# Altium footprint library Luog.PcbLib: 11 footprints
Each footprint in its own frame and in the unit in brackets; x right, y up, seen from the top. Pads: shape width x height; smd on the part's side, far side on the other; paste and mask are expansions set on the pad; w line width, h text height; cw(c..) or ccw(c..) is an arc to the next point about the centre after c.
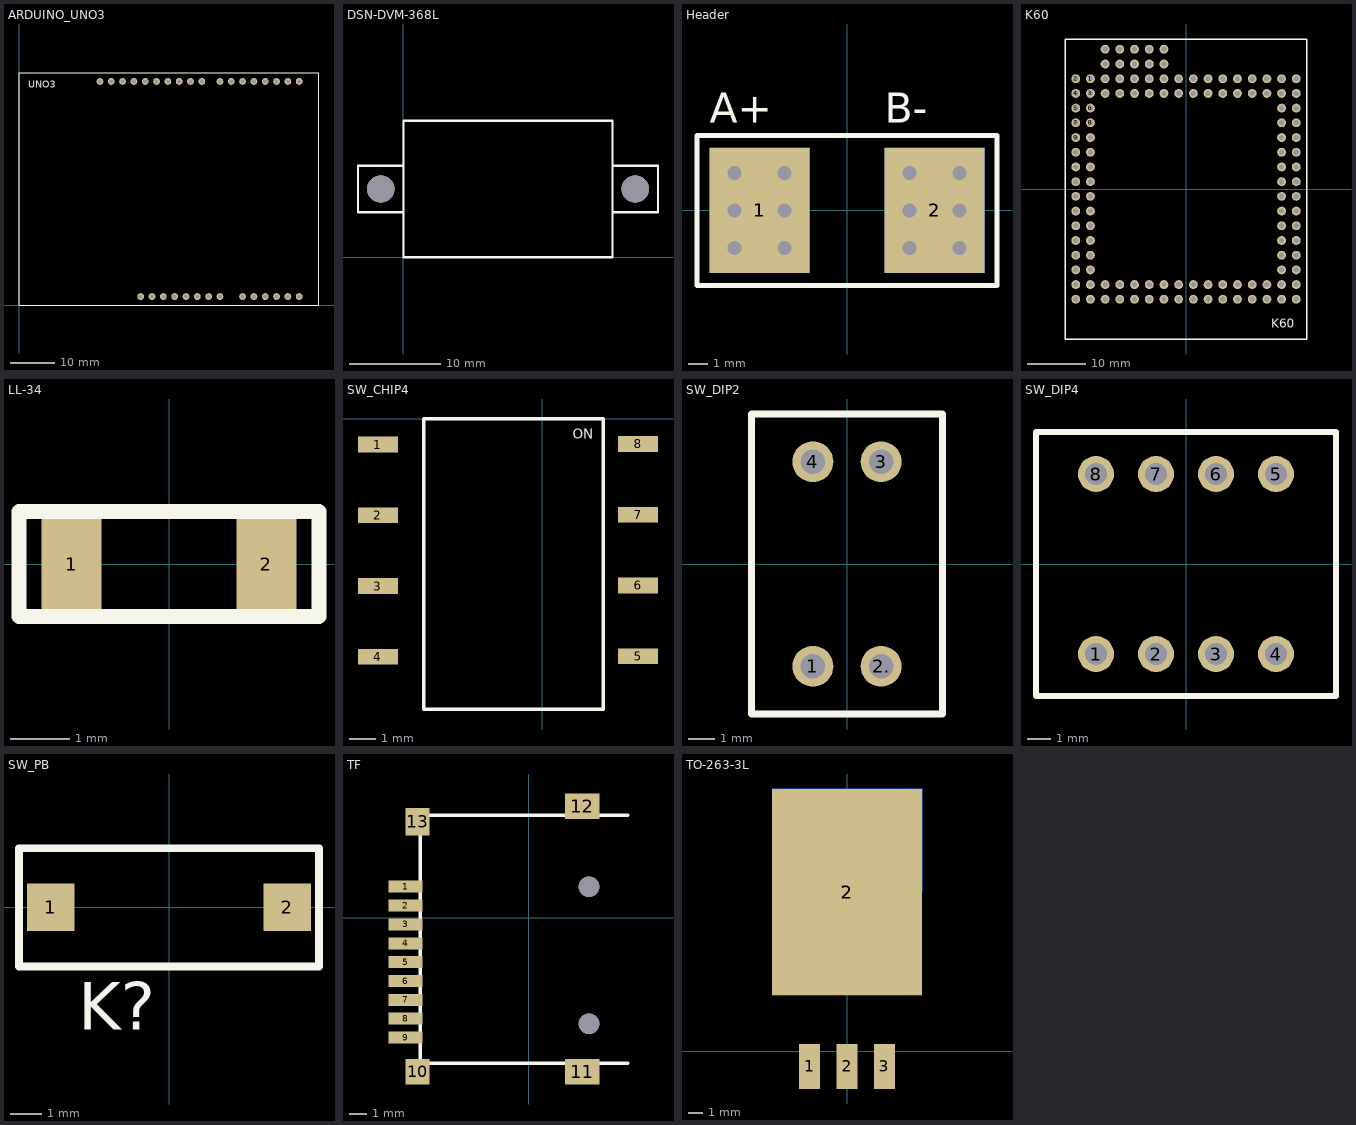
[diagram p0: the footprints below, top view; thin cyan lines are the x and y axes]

## ARDUINO_UNO3 [mil]
pads (32):
  round 60 hole 36: 1(2475,1975) 2(2375,1975) 3(2275,1975) 4(2175,1975) 5(2075,1975) 6(1975,1975) 7(1875,1975) 8(1775,1975) 9(1615,1975) 10(1515,1975) 11(1415,1975) 12(1315,1975) 13(1215,1975) 14(1115,1975) 15(1015,1975) 16(915,1975) 17(815,1975) 18(715,1975) 19(1075,75) 20(1175,75) 21(1275,75) 22(1375,75) 23(1475,75) 24(1575,75) 25(1675,75) 26(1775,75) 27(1975,75) 28(2075,75) 29(2175,75) 30(2275,75) 31(2375,75) 32(2475,75)
Top Overlay:
  lines w10: 0,0 0,2050 2650,2050 2650,0 0,0
  text "UNO3" at 80,1920 h60

## DSN-DVM-368L [mil]
height 393.7
via 1003.94,295.28 diameter 118.11 hole 118.11
via -98.43,295.28 diameter 118.11 hole 118.11
Top Overlay:
  lines w10: -0.67,395.67 -196.85,395.67 -196.85,194.88 -0.12,194.88 ; 905.63,194.88 1102.36,194.88 1102.36,395.67 906.18,395.67 ; 0,0 905.51,0 905.51,590.55 0,590.55 0,0

## Header [mil]
pads (4):
  rect 200x250 smd: 1(-175,0) 2(175,0)
  rect 200x250 smd far side: 1(-175,0) 2(175,0)
via -225,75 diameter 50 hole 28
via -125,75 diameter 50 hole 28
via -225,0 diameter 50 hole 28
via -125,0 diameter 50 hole 28
via -225,-75 diameter 50 hole 28
via -125,-75 diameter 50 hole 28
via 125,75 diameter 50 hole 28
via 225,75 diameter 50 hole 28
via 125,0 diameter 50 hole 28
via 125,-75 diameter 50 hole 28
via 225,0 diameter 50 hole 28
via 225,-75 diameter 50 hole 28
Top Overlay:
  lines w10: -300,-150 -300,150 185,150 300,150 300,-150 -185,-150 -300,-150
  text "B-" at 75,175 h60
  text "A+" at -275,175 h60

## K60 [mil]
pads (122):
  round 60 hole 36: 1(-650,750) 2(-750,750) 3(-650,650) 4(-750,650) 5(-750,550) 6(-650,550) 7(-750,450) 8(-650,450) 9(-750,350) 10(-650,350) 11(-750,250) 12(-650,250) 13(-750,150) 14(-650,150) 15(-750,50) 16(-650,50) 17(-650,-50) 18(-650,-150) 19(-750,-50) 20(-750,-150) 21(-750,-250) 22(-650,-250) 23(-750,-350) 24(-650,-350) 25(-750,-450) 26(-650,-450) 27(-650,-550) 28(-750,-550) 29(-750,-650) 30(-650,-650) 31(-750,-750) 32(-650,-750) 33(-550,-750) 34(-550,-650) 35(-450,-750) 36(-450,-650) 37(-350,-750) 38(-350,-650) 39(-250,-750) 40(-250,-650) 41(-150,-750) 42(-150,-650) 43(-50,-750) 44(-50,-650) 45(50,-650) 46(50,-750) 47(150,-750) 48(250,-750) 49(150,-650) 50(250,-650) 51(350,-650) 52(350,-750) 53(450,-650) 54(450,-750) 55(550,-650) 56(550,-750) 57(650,-650) 58(650,-750) 59(750,-650) 60(750,-750) 61(650,-550) 62(750,-550) 63(750,-450) 64(650,-450) 65(750,-350) 66(650,-350) 67(750,-250) 68(650,-250) 69(750,-150) 70(650,-150) 71(750,-50) 72(650,-50) 73(750,50) 74(650,50) 75(750,150) 76(650,150) 77(750,250) 78(650,250) 79(750,350) 80(650,350) 81(750,450) 82(650,450) 83(750,550) 84(650,550) 85(750,650) 86(650,650) 87(750,750) 88(550,750) 89(650,750) 90(550,650) 91(450,750) 92(350,750) 93(450,650) 94(250,750) 95(350,650) 96(150,750) 97(250,650) 98(150,650) 99(50,750) 100(50,650) 101(-50,750) 102(-150,750) 103(-50,650) 104(-250,750) 105(-150,650) 106(-350,750) 107(-250,650) 108(-450,750) 109(-350,650) 110(-550,750) 111(-450,650) 112(-550,650) 113(-450,950) 114(-250,950) 115(-350,950) 116(-550,950) 117(-450,850) 118(-150,950) 119(-550,850) 120(-150,850) 121(-250,850) 122(-350,850)
Top Overlay:
  lines w10: -820,-1020 -820,1020 820,1020 820,-1020 -820,-1020
  text "K60" at 580,-945 h60

## LL-34 [mil]
pads (2):
  rect 40x60 smd: 1(-65,0) 2(65,0)
Top Overlay:
  lines w10: -100,-35 100,-35 100,35 -100,35 -100,-35

## SW_CHIP4 [mil]
pads (8):
  rect 60x23.62 smd: 1(-246.83,-39) 2(-246.83,-145.33) 3(-246.83,-251.67) 4(-246.83,-358) 5(144.17,-357) 6(144.17,-250.67) 7(144.17,-144.33) 8(144.17,-38)
Top Overlay:
  lines w5: -178,-437 92,-437 92,0 -178,0 -178,-437
  text "ON" at 46,-30 h15

## SW_DIP2 [mil]
pads (4):
  round 60 hole 36: 1(-50,-150) 2.(50,-150) 3(50,150) 4(-50,150)
Top Overlay:
  lines w10: -140,-220 -140,220 140,220 140,-220 -140,-220

## SW_DIP4 [mil]
pads (8):
  round 60 hole 36: 1(-150,-150) 2(-50,-150) 3(50,-150) 4(150,-150) 5(150,150) 6(50,150) 7(-50,150) 8(-150,150)
Top Overlay:
  lines w10: -250,-220 250,-220 250,220 -250,220 -250,-220

## SW_PB [mil]
pads (2):
  rect 60x60 smd: 1(-150,0) 2(150,0)
Top Overlay:
  lines w10: -190,-75 -190,75 190,75 190,-75 -190,-75
  text "K?" at -115,-155 h60

## TF [mm]
pads (15):
  rect 2x0.7 smd: 1(-7.2,1.8) 2(-7.2,0.7) 3(-7.2,-0.4) 4(-7.2,-1.5) 5(-7.2,-2.6) 6(-7.2,-3.7) 7(-7.2,-4.8) 8(-7.2,-5.9) 9(-7.2,-7)
  rect 1.4x1.5 smd: 10(-6.5,-9)
  rect 2x1.5 smd: 11(3.1,-9) 12(3.1,6.5)
  rect 1.4x1.6 smd: 13(-6.5,5.6)
  round 1.2 hole 1.2 unplated: ""(3.5,-6.2)
  round 1.2 hole 1.2: ""(3.5,1.8)
Top Overlay:
  lines w0.2: 5.75,-8.509 -6.35,-8.509 -6.35,5.969 5.75,5.969

## TO-263-3L [mil]
pads (5):
  rect 55x120 smd: 1(-100,-40) 2(0,-40) 3(100,-40)
  rect 400x550 smd: 2(0,425)
  rect 400x550 smd far side: 2(0,425)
